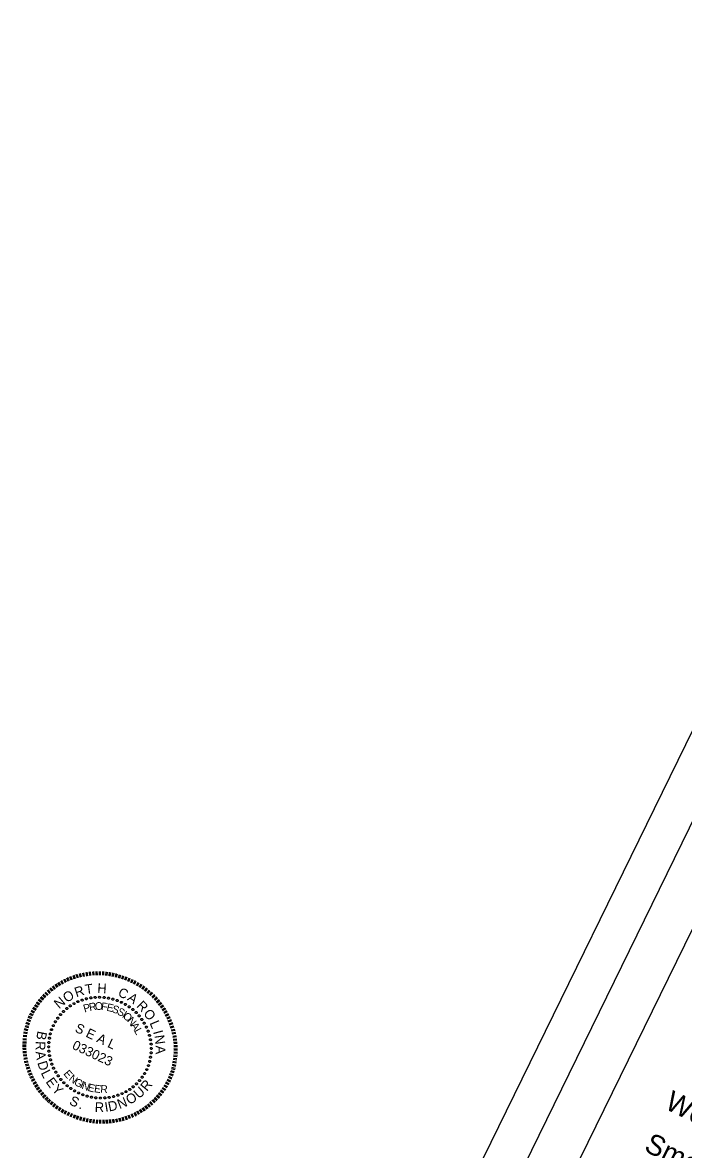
# Model space of a CAD drawing. Extents: x 1517888 to 1526099, y 633375 to 640181.
# Drawn here: x 1521910 to 1522473, y 636952 to 637911 of the extents above; entities that cross this region are included whole.
import ezdxf

# ---------------------------------------------------------------- set-up
doc = ezdxf.new("R2010")
doc.units = 0
for name, color, linetype in [('Default', 7, 'Continuous'), ('Old_Level_2', 7, 'Continuous'), ('Sheet Plot Border Outside CELL', 7, 'Continuous')]:
    doc.layers.add(name, color=color, linetype=linetype)

msp = doc.modelspace()

# ---------------------------------------------------------------- linework, layer by layer
at = {"layer": 'Default'}
for p, q in [((1522921.02, 638209.21), (1521963.55, 636251.51)), ((1522062.93, 636285.61), (1522955.11, 638109.83))]:
    msp.add_line(p, q, dxfattribs=at)
at = {"layer": 'Old_Level_2'}
for p, q in [((1521951.77, 637095.78), (1521950.57, 637098.68)), ((1521952.65, 637096.14), (1521951.41, 637098.97)), ((1521954.34, 637096.72), (1521953.24, 637099.65)), ((1521955.22, 637097.08), (1521954.09, 637099.94)), ((1521956.96, 637097.56), (1521955.96, 637100.52)), ((1521957.8, 637097.85), (1521956.88, 637100.78)), ((1521959.57, 637098.22), (1521958.72, 637101.29)), ((1521960.49, 637098.47), (1521959.6, 637101.47)), ((1521962.19, 637098.88), (1521961.48, 637101.88)), ((1521963.07, 637099.06), (1521962.47, 637102.1)), ((1521964.88, 637099.33), (1521964.31, 637102.44)), ((1521965.84, 637099.48), (1521965.24, 637102.52)), ((1521967.62, 637099.67), (1521967.15, 637102.82)), ((1521968.5, 637099.86), (1521968.08, 637102.9)), ((1521970.32, 637099.95), (1521970, 637103.03)), ((1521971.25, 637100.03), (1521970.92, 637103.11)), ((1521973.06, 637100.12), (1521972.92, 637103.2)), ((1521973.95, 637100.13), (1521973.81, 637103.21)), ((1521975.81, 637100.11), (1521975.77, 637103.23)), ((1521976.7, 637100.12), (1521976.74, 637103.21)), ((1521978.52, 637100.04), (1521978.63, 637103.09)), ((1521979.45, 637099.94), (1521979.59, 637103.06)), ((1521981.24, 637099.79), (1521981.53, 637102.84)), ((1521982.17, 637099.69), (1521982.46, 637102.74)), ((1521984, 637099.43), (1521984.39, 637102.52)), ((1521984.93, 637099.34), (1521985.32, 637102.43)), ((1521986.66, 637099.04), (1521987.26, 637102.03)), ((1521987.63, 637098.84), (1521988.16, 637101.86)), ((1521989.39, 637098.44), (1521990.1, 637101.46)), ((1521990.29, 637098.28), (1521990.97, 637101.23)), ((1521992.09, 637097.77), (1521992.87, 637100.76)), ((1521992.95, 637097.54), (1521993.81, 637100.49)), ((1521994.72, 637096.96), (1521995.65, 637099.88)), ((1521995.58, 637096.73), (1521996.52, 637099.64)), ((1521997.32, 637096.08), (1521998.32, 637098.96)), ((1521998.22, 637095.74), (1521999.23, 637098.62)), ((1521935.52, 637086.32), (1521933.47, 637088.75)), ((1521936.24, 637086.93), (1521934.16, 637089.28)), ((1521937.63, 637087.99), (1521935.69, 637090.46)), ((1521938.4, 637088.49), (1521936.46, 637090.96)), ((1521939.86, 637089.52), (1521938.06, 637092.09)), ((1521940.56, 637090.06), (1521938.83, 637092.59)), ((1521942.13, 637090.95), (1521940.36, 637093.59)), ((1521942.9, 637091.45), (1521941.13, 637094.09)), ((1521944.47, 637092.34), (1521942.84, 637095.09)), ((1521945.24, 637092.84), (1521943.65, 637095.48)), ((1521946.85, 637093.63), (1521945.4, 637096.38)), ((1521947.66, 637094.02), (1521946.21, 637096.77)), ((1521949.24, 637094.74), (1521947.93, 637097.6)), ((1521950.15, 637095.17), (1521948.81, 637097.96)), ((1521999.85, 637095.06), (1522001.04, 637097.94)), ((1522000.76, 637094.72), (1522001.91, 637097.53)), ((1522002.35, 637093.97), (1522003.65, 637096.71)), ((1522003.22, 637093.55), (1522004.52, 637096.3)), ((1522004.86, 637092.7), (1522006.33, 637095.45)), ((1522005.66, 637092.32), (1522007.1, 637095)), ((1522007.26, 637091.39), (1522008.77, 637094.04)), ((1522008.1, 637090.91), (1522009.61, 637093.56)), ((1522009.59, 637089.95), (1522011.25, 637092.52)), ((1522010.43, 637089.47), (1522012.09, 637092.04)), ((1522011.89, 637088.43), (1522013.7, 637090.94)), ((1522012.7, 637087.88), (1522014.5, 637090.39)), ((1522014.13, 637086.78), (1522016.08, 637089.21)), ((1522014.86, 637086.26), (1522016.77, 637088.63)), ((1521926.73, 637077.47), (1521924.2, 637079.44)), ((1521927.82, 637078.85), (1521925.4, 637080.85)), ((1521928.44, 637079.59), (1521926.01, 637081.59)), ((1521929.64, 637080.83), (1521927.28, 637082.97)), ((1521930.23, 637081.5), (1521927.94, 637083.61)), ((1521931.5, 637082.71), (1521929.28, 637084.96)), ((1521932.16, 637083.34), (1521929.94, 637085.59)), ((1521933.44, 637084.55), (1521931.36, 637086.91)), ((1521934.17, 637085.15), (1521931.98, 637087.47)), ((1522016.26, 637085.08), (1522018.32, 637087.38)), ((1522017.03, 637084.46), (1522019.01, 637086.8)), ((1522018.35, 637083.32), (1522020.45, 637085.52)), ((1522019.02, 637082.66), (1522021.15, 637084.93)), ((1522020.38, 637081.42), (1522022.55, 637083.58)), ((1522021.01, 637080.69), (1522023.18, 637082.85)), ((1522022.27, 637079.41), (1522024.59, 637081.5)), ((1522022.93, 637078.75), (1522025.22, 637080.77)), ((1522024.05, 637077.36), (1522026.48, 637079.31)), ((1521920.29, 637067.77), (1521917.53, 637069.24)), ((1521920.76, 637068.58), (1521917.93, 637070.09)), ((1521921.67, 637070.13), (1521918.87, 637071.71)), ((1521922.04, 637070.9), (1521919.34, 637072.52)), ((1521923.02, 637072.42), (1521920.35, 637074.11)), ((1521923.56, 637073.2), (1521920.9, 637074.88)), ((1521924.51, 637074.64), (1521921.98, 637076.44)), ((1521925.05, 637075.42), (1521922.49, 637077.14)), ((1521926.15, 637076.8), (1521923.65, 637078.66)), ((1522024.69, 637076.63), (1522027.11, 637078.59)), ((1522025.8, 637075.24), (1522028.27, 637077.09)), ((1522026.36, 637074.55), (1522028.87, 637076.29)), ((1522027.45, 637073.09), (1522030.03, 637074.8)), ((1522027.98, 637072.33), (1522030.56, 637074.04)), ((1522029.03, 637070.8), (1522031.65, 637072.4)), ((1522029.52, 637069.96), (1522032.17, 637071.64)), ((1522030.43, 637068.5), (1522033.16, 637069.97)), ((1521916.5, 637058.79), (1521913.51, 637059.78)), ((1521917.12, 637060.48), (1521914.09, 637061.57)), ((1521917.34, 637061.32), (1521914.41, 637062.45)), ((1521918.03, 637062.98), (1521915.14, 637064.17)), ((1521918.43, 637063.82), (1521915.46, 637065.05)), ((1521919.09, 637065.41), (1521916.26, 637066.74)), ((1521919.49, 637066.25), (1521916.66, 637067.59)), ((1522030.92, 637067.67), (1522033.58, 637069.17)), ((1522031.76, 637066.06), (1522034.57, 637067.5)), ((1522032.18, 637065.26), (1522034.95, 637066.63)), ((1522033.02, 637063.66), (1522035.83, 637064.92)), ((1522033.41, 637062.79), (1522036.25, 637064.12)), ((1522034.07, 637061.19), (1522037, 637062.31)), ((1522034.46, 637060.32), (1522037.42, 637061.5)), ((1522035.2, 637058.68), (1522038.09, 637059.73)), ((1521914.27, 637050.12), (1521911.18, 637050.71)), ((1521914.45, 637051.07), (1521911.33, 637051.59)), ((1521914.82, 637052.79), (1521911.77, 637053.45)), ((1521915.04, 637053.63), (1521911.95, 637054.4)), ((1521915.52, 637055.38), (1521912.42, 637056.16)), ((1521915.66, 637056.26), (1521912.67, 637057.07)), ((1521916.18, 637057.91), (1521913.18, 637058.9)), ((1522035.48, 637057.77), (1522038.37, 637058.82)), ((1522036.03, 637056.13), (1522039, 637056.97)), ((1522036.32, 637055.22), (1522039.32, 637056.13)), ((1522036.84, 637053.51), (1522039.85, 637054.25)), ((1522037.05, 637052.64), (1522040.06, 637053.37)), ((1522037.47, 637050.89), (1522040.51, 637051.52)), ((1522037.68, 637050.02), (1522040.79, 637050.61)), ((1521913.4, 637040.37), (1521910.26, 637040.48)), ((1521913.52, 637042.12), (1521910.34, 637042.33)), ((1521913.52, 637043.07), (1521910.41, 637043.25)), ((1521913.64, 637044.82), (1521910.49, 637045.1)), ((1521913.71, 637045.73), (1521910.56, 637046.01)), ((1521913.94, 637047.52), (1521910.78, 637047.98)), ((1521914.01, 637048.43), (1521910.93, 637048.85)), ((1522038.09, 637048.27), (1522041.15, 637048.73)), ((1522038.2, 637047.36), (1522041.35, 637047.85)), ((1522038.51, 637045.58), (1522041.6, 637045.93)), ((1522038.61, 637044.67), (1522041.7, 637045.02)), ((1522038.85, 637042.92), (1522041.95, 637043.1)), ((1522038.92, 637041.94), (1522041.98, 637042.22)), ((1521913.46, 637037.68), (1521910.32, 637037.61)), ((1521913.4, 637039.43), (1521910.33, 637039.5)), ((1521913.49, 637036.8), (1521910.39, 637036.63)), ((1521913.62, 637035.02), (1521910.49, 637034.77)), ((1521913.69, 637034.04), (1521910.6, 637033.86)), ((1521913.93, 637032.29), (1521910.77, 637031.97)), ((1521914.04, 637031.38), (1521910.95, 637031.03)), ((1522038.83, 637031.23), (1522041.98, 637030.95)), ((1522038.91, 637032.14), (1522042.06, 637031.86)), ((1522038.98, 637040.19), (1522042.15, 637040.33)), ((1522039.01, 637039.32), (1522042.15, 637039.39)), ((1522039.03, 637034.84), (1522042.21, 637034.63)), ((1522039.03, 637033.89), (1522042.14, 637033.71)), ((1522039.07, 637036.62), (1522042.25, 637036.59)), ((1522039.08, 637037.57), (1522042.22, 637037.46)), ((1521914.28, 637029.63), (1521911.22, 637029.18)), ((1521914.49, 637028.76), (1521911.4, 637028.23)), ((1521914.8, 637026.97), (1521911.75, 637026.34)), ((1521915.01, 637026.1), (1521911.96, 637025.47)), ((1521915.42, 637024.35), (1521912.42, 637023.62)), ((1521915.71, 637023.45), (1521912.7, 637022.71)), ((1521916.23, 637021.74), (1521913.26, 637020.9)), ((1522037.06, 637021.64), (1522040.13, 637020.8)), ((1522037.5, 637023.33), (1522040.53, 637022.59)), ((1522037.65, 637024.21), (1522040.78, 637023.51)), ((1522038.02, 637025.93), (1522041.14, 637025.4)), ((1522038.2, 637026.88), (1522041.29, 637026.28)), ((1522038.5, 637028.63), (1522041.62, 637028.1)), ((1522038.64, 637029.51), (1522041.69, 637029.02)), ((1521916.51, 637020.83), (1521913.47, 637020.02)), ((1521917.07, 637019.19), (1521914.11, 637018.18)), ((1521917.35, 637018.28), (1521914.49, 637017.3)), ((1521918.01, 637016.68), (1521915.16, 637015.53)), ((1521918.4, 637015.81), (1521915.55, 637014.65)), ((1521919.13, 637014.17), (1521916.32, 637012.91)), ((1521919.52, 637013.3), (1521916.71, 637012.04)), ((1521920.29, 637011.73), (1521917.59, 637010.33)), ((1522034.12, 637013.14), (1522037.01, 637011.94)), ((1522034.44, 637014.02), (1522037.41, 637012.79)), ((1522035.13, 637015.67), (1522038.13, 637014.51)), ((1522035.43, 637016.48), (1522038.39, 637015.43)), ((1522036.04, 637018.17), (1522039.04, 637017.18)), ((1522036.37, 637019.05), (1522039.37, 637018.06)), ((1522036.81, 637020.73), (1522039.87, 637019.89)), ((1521920.78, 637010.89), (1521917.98, 637009.46)), ((1521921.62, 637009.29), (1521918.89, 637007.83)), ((1521922.12, 637008.46), (1521919.39, 637006.99)), ((1521923.02, 637007), (1521920.37, 637005.32)), ((1521923.52, 637006.16), (1521920.9, 637004.56)), ((1521924.5, 637004.67), (1521921.99, 637002.92)), ((1521925.1, 637003.87), (1521922.52, 637002.16)), ((1521926.11, 637002.44), (1521923.67, 637000.67)), ((1522027.97, 637002.35), (1522030.56, 637000.52)), ((1522028.99, 637003.76), (1522031.65, 637002.08)), ((1522029.53, 637004.54), (1522032.19, 637002.85)), ((1522030.44, 637006.09), (1522033.13, 637004.48)), ((1522030.88, 637006.83), (1522033.61, 637005.29)), ((1522031.79, 637008.38), (1522034.55, 637006.91)), ((1522032.18, 637009.23), (1522035.02, 637007.72)), ((1522032.99, 637010.74), (1522035.89, 637009.37)), ((1522033.39, 637011.59), (1522036.29, 637010.22)), ((1521926.67, 637001.75), (1521924.2, 636999.9)), ((1521927.86, 637000.33), (1521925.43, 636998.37)), ((1521928.49, 636999.6), (1521926.06, 636997.65)), ((1521929.61, 636998.21), (1521927.33, 636996.19)), ((1521930.28, 636997.55), (1521927.96, 636995.46)), ((1521931.53, 636996.27), (1521929.36, 636994.11)), ((1521932.17, 636995.54), (1521929.99, 636993.38)), ((1521933.46, 636994.33), (1521931.36, 636992.14)), ((1521934.2, 636993.64), (1521932.02, 636991.48)), ((1521935.52, 636992.5), (1521933.53, 636990.16)), ((1522020.39, 636993.62), (1522022.61, 636991.36)), ((1522021.04, 636994.25), (1522023.26, 636992)), ((1522022.25, 636995.49), (1522024.61, 636993.35)), ((1522022.9, 636996.13), (1522025.19, 636994.02)), ((1522024.07, 636997.47), (1522026.46, 636995.4)), ((1522024.65, 636998.15), (1522027.15, 636996.11)), ((1522025.82, 636999.49), (1522028.35, 636997.52)), ((1522026.4, 637000.16), (1522028.89, 636998.3)), ((1522027.45, 637001.65), (1522030.05, 636999.82)), ((1521936.22, 636991.91), (1521934.23, 636989.58)), ((1521937.61, 636990.73), (1521935.77, 636988.33)), ((1521938.42, 636990.18), (1521936.47, 636987.74)), ((1521939.85, 636989.08), (1521938.05, 636986.57)), ((1521940.65, 636988.53), (1521938.85, 636986.02)), ((1521942.12, 636987.49), (1521940.46, 636984.92)), ((1521942.88, 636987.05), (1521941.22, 636984.47)), ((1521944.45, 636986.05), (1521942.86, 636983.44)), ((1521945.29, 636985.57), (1521943.7, 636982.96)), ((1521946.82, 636984.67), (1521945.38, 636981.99)), ((1521947.69, 636984.26), (1521946.25, 636981.58)), ((1521949.25, 636983.44), (1521947.96, 636980.69)), ((1521950.12, 636983.03), (1521948.83, 636980.28)), ((1522004.89, 636982.94), (1522006.34, 636980.19)), ((1522005.69, 636983.33), (1522007.14, 636980.58)), ((1522007.27, 636984.22), (1522008.9, 636981.48)), ((1522008.07, 636984.62), (1522009.66, 636981.97)), ((1522009.65, 636985.51), (1522011.34, 636982.9)), ((1522010.41, 636986.01), (1522012.11, 636983.4)), ((1522011.92, 636986.94), (1522013.72, 636984.37)), ((1522012.68, 636987.44), (1522014.52, 636984.94)), ((1522014.15, 636988.47), (1522016.09, 636986)), ((1522014.84, 636989), (1522016.78, 636986.54)), ((1522016.23, 636990.07), (1522018.31, 636987.71)), ((1522017.03, 636990.64), (1522019.01, 636988.24)), ((1522018.38, 636991.81), (1522020.49, 636989.52)), ((1522019.04, 636992.45), (1522021.19, 636990.05)), ((1521951.82, 636982.31), (1521950.64, 636979.43)), ((1521952.62, 636981.94), (1521951.47, 636979.12)), ((1521954.32, 636981.22), (1521953.25, 636978.37)), ((1521955.23, 636980.88), (1521954.15, 636978.03)), ((1521956.89, 636980.27), (1521955.96, 636977.35)), ((1521957.83, 636980), (1521956.89, 636977.08)), ((1521959.52, 636979.46), (1521958.73, 636976.47)), ((1521960.46, 636979.19), (1521959.67, 636976.2)), ((1521962.19, 636978.71), (1521961.58, 636975.73)), ((1521963.16, 636978.52), (1521962.44, 636975.5)), ((1521964.92, 636978.11), (1521964.38, 636975.1)), ((1521965.82, 636977.95), (1521965.28, 636974.93)), ((1521967.61, 636977.62), (1521967.22, 636974.53)), ((1521968.54, 636977.52), (1521968.15, 636974.44)), ((1521970.3, 636977.3), (1521970.09, 636974.21)), ((1521971.3, 636977.17), (1521971.02, 636974.12)), ((1521973.09, 636977.01), (1521972.95, 636973.9)), ((1521973.95, 636976.95), (1521973.92, 636973.87)), ((1521975.77, 636976.87), (1521975.81, 636973.75)), ((1521976.74, 636976.85), (1521976.7, 636973.76)), ((1521978.52, 636976.87), (1521978.66, 636973.78)), ((1521979.48, 636976.84), (1521979.63, 636973.76)), ((1521981.3, 636976.93), (1521981.55, 636973.89)), ((1521982.23, 636977.01), (1521982.55, 636973.93)), ((1521983.97, 636977.14), (1521984.4, 636974.09)), ((1521984.93, 636977.29), (1521985.32, 636974.17)), ((1521986.7, 636977.48), (1521987.31, 636974.44)), ((1521987.66, 636977.63), (1521988.16, 636974.56)), ((1521989.4, 636977.93), (1521990.11, 636974.93)), ((1521990.28, 636978.12), (1521991, 636975.11)), ((1521992.06, 636978.49), (1521992.95, 636975.48)), ((1521992.97, 636978.74), (1521993.83, 636975.67)), ((1521994.67, 636979.15), (1521995.67, 636976.18)), ((1521995.59, 636979.4), (1521996.51, 636976.47)), ((1521997.36, 636979.95), (1521998.38, 636977.05)), ((1521998.2, 636980.24), (1521999.3, 636977.31)), ((1521999.89, 636980.82), (1522001.13, 636977.99)), ((1522000.77, 636981.18), (1522001.98, 636978.28)), ((1522002.35, 636981.89), (1522003.74, 636979)), ((1522003.23, 636982.25), (1522004.55, 636979.4))]:
    msp.add_line(p, q, dxfattribs=at)
for centre in [(1521960.95, 637078.91), (1521964.58, 637079.98), (1521968.3, 637080.73), (1521972.07, 637081.16), (1521975.88, 637081.26), (1521979.69, 637081.04), (1521983.47, 637080.49), (1521987.2, 637079.63), (1521990.85, 637078.45), (1521945.07, 637069.18), (1521947.86, 637071.67), (1521950.87, 637073.9), (1521954.07, 637075.86), (1521957.44, 637077.53), (1521994.38, 637076.96), (1521997.77, 637075.18), (1522001, 637073.12), (1522004.05, 637070.8), (1522006.88, 637068.23), (1521938.19, 637060.41), (1521940.22, 637063.53), (1521942.52, 637066.47), (1522009.47, 637065.43), (1522011.81, 637062.42), (1522013.89, 637059.24), (1521933.9, 637050.14), (1521935.02, 637053.69), (1521936.46, 637057.12), (1522015.67, 637055.89), (1522017.16, 637052.41), (1521932.63, 637042.8), (1521933.1, 637046.5), (1522018.33, 637048.83), (1522019.18, 637045.16), (1522019.71, 637041.45), (1521932.5, 637039.06), (1521932.69, 637035.32), (1521933.21, 637031.61), (1522019.29, 637030.27), (1522019.76, 637033.97), (1522019.9, 637037.71), (1521934.07, 637027.94), (1521935.24, 637024.36), (1521936.72, 637020.88), (1522017.37, 637023.09), (1522018.49, 637026.64), (1521938.51, 637017.54), (1521940.58, 637014.35), (1521942.92, 637011.35), (1522012.18, 637013.24), (1522014.2, 637016.36), (1522015.94, 637019.65), (1521945.52, 637008.55), (1521948.35, 637005.98), (1521951.39, 637003.65), (1521954.62, 637001.59), (1522001.52, 637002.88), (1522004.53, 637005.11), (1522007.32, 637007.59), (1522009.88, 637010.31), (1521958.02, 636999.81), (1521961.55, 636998.33), (1521965.19, 636997.15), (1521968.92, 636996.28), (1521972.7, 636995.73), (1521976.51, 636995.51), (1521980.32, 636995.61), (1521984.1, 636996.04), (1521987.81, 636996.8), (1521991.44, 636997.86), (1521994.95, 636999.24), (1521998.32, 637000.92)]:
    msp.add_ellipse(centre, major_axis=(0.823, -0.388), ratio=0.970588, dxfattribs=at)
at = {"layer": 'Sheet Plot Border Outside CELL'}
msp.add_lwpolyline([(1525964.29, 636688.25), (1522938.76, 638167.97), (1521972.2, 636191.69), (1524997.73, 634711.97)], close=True, dxfattribs=at)

# ---------------------------------------------------------------- texts
at = {"layer": 'Default'}
for s, p in [('Well', (1522456.05, 636986.78)), ('Small Mine', (1522438.47, 636950.85))]:
    msp.add_text(s, height=17.49, rotation=333.93772, dxfattribs=at).set_placement(p)
at = {"layer": 'Old_Level_2'}
for s, height, rotation, p in [('R', 8.25, 18.30762, (1521956.07, 637081.19)), ('T', 8.2, 7.95241, (1521964.04, 637083.8)), ('H', 8.13, 356.76499, (1521973.77, 637085.07)), ('C', 8.06, 335.54521, (1521990.87, 637082.6)), ('N', 8.31, 40.32106, (1521941.4, 637070.98)), ('O', 8.3, 32.93215, (1521947.92, 637076.34)), ('A', 8.08, 324.74938, (1521998.94, 637079.22)), ('P', 6.62, 16.85251, (1521963.08, 637068.24)), ('R', 6.59, 10.70401, (1521967.46, 637069.45)), ('O', 6.56, 4.59292, (1521972.11, 637070.27)), ('F', 6.51, 352.46702, (1521976.85, 637070.53)), ('E', 6.49, 346.44092, (1521981.36, 637069.95)), ('S', 6.47, 340.43015, (1521985.79, 637068.81)), ('S', 6.47, 334.42699, (1521990.31, 637066.93)), ('I', 6.47, 328.42338, (1521994.5, 637064.53)), ('R', 8.12, 314.33822, (1522006.74, 637073.56)), ('O', 8.17, 307.21442, (1522012.7, 637067.39)), ('O', 6.49, 322.41133, (1521995.16, 637064.05)), ('N', 6.54, 310.33173, (1521998.8, 637061.04)), ('L', 8.25, 292.82783, (1522018.26, 637059.43)), ('B', 8.25, 258.64176, (1521923.2, 637052.98)), ('S E A L', 8.091, 334.75051, (1521954.19, 637052.29)), ('A', 6.56, 304.251, (1522002, 637057.12)), ('L', 6.59, 298.13602, (1522004.97, 637052.88)), ('I', 8.28, 285.5549, (1522021.27, 637051.9)), ('R', 8.25, 268.15709, (1521921.52, 637044.02)), ('033023', 8.091, 334.75051, (1521951.89, 637037.72)), ('N', 8.3, 278.22758, (1522022.46, 637048.59)), ('A', 8.25, 277.67243, (1521921.34, 637034.9)), ('A', 8.31, 270.84932, (1522023.54, 637040.16)), ('D', 8.25, 287.50495, (1521922.74, 637025.58)), ('L', 8.25, 297.02028, (1521925.59, 637016.92)), ('E', 8.25, 306.05985, (1521929.59, 637009.24)), ('E', 6.54, 309.6777, (1521944.76, 637016.03)), ('N', 6.49, 321.76236, (1521949.14, 637011.04)), ('G', 6.47, 327.7758, (1521953.51, 637007.51)), ('Y', 8.25, 315.09943, (1521934.75, 637002.28)), ('I', 6.47, 333.77993, (1521958.61, 637004.59)), ('N', 6.47, 339.78275, (1521960.07, 637003.56)), ('E', 6.48, 345.79232, (1521965.31, 637001.69)), ('E', 6.5, 351.81642, (1521970.88, 637000.53)), ('R', 6.53, 357.86226, (1521976.39, 636999.99)), ('U', 8.25, 41.05464, (1522009.29, 636994.5)), ('R', 8.25, 50.72857, (1522016.2, 637000.68)), ('S', 8.25, 334.84375, (1521949.39, 636990.4)), ('D', 8.25, 12.19145, (1521984, 636983.97)), ('N', 8.25, 21.70679, (1521992.88, 636986.01)), ('O', 8.25, 31.22213, (1522001.31, 636989.49)), ('.', 8.25, 344.35909, (1521957.69, 636986.63)), ('R', 8.25, 359.34575, (1521971.7, 636983.6)), ('I', 8.25, 8.86108, (1521980.82, 636983.61))]:
    msp.add_text(s, height=height, rotation=rotation, dxfattribs=at).set_placement(p)

doc.saveas('drawing.dxf')
